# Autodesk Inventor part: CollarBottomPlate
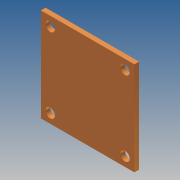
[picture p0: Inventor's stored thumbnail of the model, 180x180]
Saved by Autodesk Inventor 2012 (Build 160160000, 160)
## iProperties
Created: 2007-12
Part Number: CollarBottomPlate
Document SubType Name: Modeling
Designer: MJ
Stock Number: D-623-009-b
Material: Aluminum-6061
Density: 2.71 g/cm^3
Engineer: MJ
Mass: 268.836 g
Surface Area: 354.838 cm^2
Volume: 99.2016 cm^3
RuleStatus: InUse
Title: DgPr Assembly Cell
Author: MJ
Comments: 10 GUAGE X 1.88" X 1.88"
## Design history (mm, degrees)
sketch "Sketch1"
  geometry: L1 (0, -71.12)-(0, 71.12) reference; L2 (-71.12, 0)-(71.12, 0) reference; L3 (-63.5, 63.5)-(63.5, 63.5); L4 (63.5, 63.5)-(63.5, -63.5); L5 (63.5, -63.5)-(-63.5, -63.5); L6 (-63.5, -63.5)-(-63.5, 63.5); L7 (63.5, -63.5)-(-63.5, 63.5); 1 further point
  constraints: 10 end point, 2 parallel, 1 horizontal, 1 midpoint, 1 perpendicular, 1 vertical alignment
  dimensions: "d0" = 127 distance between parallel lines of L4 L6 (derived)
extrude "Extrusion1" new body sketch "Sketch1" taper "d3" = 0 deg
hole "BoltHole" stored, may be unused: countersink angle "d10" = 82 deg, drill point angle "d12" = 118 deg; dims "d7" = 19.05, "d8" = 9.525, "d9" = 6.35, "d11" = 25.4
pattern_linear "BoltHolePattern"
body "Solid1"
